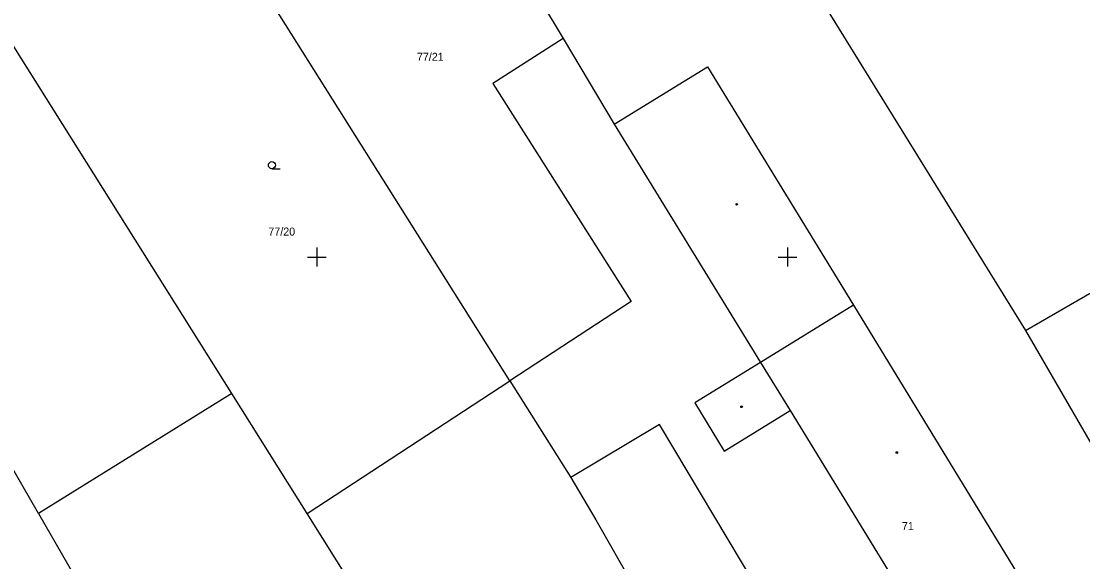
# Model space of a CAD drawing. Extents: x -703403 to -701924, y -1022520 to -1021856.
# Drawn here: x -703265.7 to -703209.3, y -1022116.2 to -1022087.5 of the extents above; entities that cross this region are included whole.
import ezdxf

# ---------------------------------------------------------------- set-up
doc = ezdxf.new("R2010")
doc.units = 0
for name, color, linetype in [('Z_hektometricka_sit', 7, 'Continuous'), ('Z_katastr_cisla_pozemkova', 7, 'Continuous'), ('Z_katastr_cisla_stavebni', 7, 'Continuous'), ('Z_katastr_hranice', 7, 'Continuous'), ('Z_katastr_vnitrni_kresba', 7, 'Continuous'), ('Z_katastr_znacky_budov', 7, 'Continuous'), ('Z_katastr_znacky_kultur', 7, 'Continuous')]:
    doc.layers.add(name, color=color, linetype=linetype)

msp = doc.modelspace()

# ---------------------------------------------------------------- linework, layer by layer
at = {"layer": 'Z_hektometricka_sit'}
for p, q in [((-703250, -1022099.5), (-703250, -1022100.5)), ((-703225, -1022099.5), (-703225, -1022100.5)), ((-703250.5, -1022100), (-703249.5, -1022100)), ((-703225.5, -1022100), (-703224.5, -1022100))]:
    msp.add_line(p, q, dxfattribs=at)
at = {"layer": 'Z_katastr_hranice'}
for p, q in [((-703239.74, -1022106.58), (-703257.17, -1022078.89)), ((-703241, -1022081.57), (-703236.91, -1022088.4)), ((-703254.52, -1022107.24), (-703270.24, -1022082.23)), ((-703223.09, -1022086.56), (-703212.35, -1022103.9)), ((-703236.91, -1022088.4), (-703240.66, -1022090.79)), ((-703236.91, -1022088.4), (-703234.2, -1022092.94)), ((-703240.66, -1022090.79), (-703233.3, -1022102.36)), ((-703234.2, -1022092.94), (-703226.43, -1022105.6)), ((-703264.78, -1022113.62), (-703274.77, -1022096.33)), ((-703233.3, -1022102.36), (-703239.74, -1022106.58)), ((-703212.35, -1022103.9), (-703205.53, -1022115.72)), ((-703226.43, -1022105.6), (-703224.86, -1022108.15)), ((-703250.51, -1022113.62), (-703239.74, -1022106.58)), ((-703239.74, -1022106.58), (-703236.51, -1022111.71)), ((-703254.52, -1022107.24), (-703264.78, -1022113.62)), ((-703250.51, -1022113.62), (-703254.52, -1022107.24)), ((-703224.86, -1022108.15), (-703216.18, -1022122.3)), ((-703236.51, -1022111.71), (-703235.18, -1022113.95)), ((-703264.78, -1022113.62), (-703258.11, -1022125.18)), ((-703247.48, -1022118.45), (-703250.51, -1022113.62)), ((-703235.18, -1022113.95), (-703226.74, -1022128.73))]:
    msp.add_line(p, q, dxfattribs=at)
at = {"layer": 'Z_katastr_vnitrni_kresba'}
for p, q in [((-703234.2, -1022092.94), (-703229.25, -1022089.9)), ((-703229.25, -1022089.9), (-703221.49, -1022102.56)), ((-703212.35, -1022103.9), (-703207.38, -1022101.01)), ((-703221.49, -1022102.56), (-703226.43, -1022105.6)), ((-703221.49, -1022102.56), (-703211.28, -1022119.27)), ((-703226.43, -1022105.6), (-703229.93, -1022107.74)), ((-703229.93, -1022107.74), (-703228.36, -1022110.3)), ((-703228.36, -1022110.3), (-703224.86, -1022108.15)), ((-703231.79, -1022108.89), (-703236.51, -1022111.71)), ((-703221.73, -1022125.72), (-703231.79, -1022108.89))]:
    msp.add_line(p, q, dxfattribs=at)
at = {"layer": 'Z_katastr_znacky_budov'}
for centre in [(-703227.702, -1022097.2), (-703227.442, -1022107.95), (-703219.192, -1022110.38)]:
    msp.add_circle(centre, 0.0437, dxfattribs=at)
at = {"layer": 'Z_katastr_znacky_kultur'}
msp.add_line((-703252.388, -1022095.31), (-703251.951, -1022095.31), dxfattribs=at)
msp.add_circle((-703252.388, -1022095.122), 0.187, dxfattribs=at)

# ---------------------------------------------------------------- texts
at = {"layer": 'Z_katastr_cisla_pozemkova'}
for s, p in [('77/21', (-703244.684, -1022089.58)), ('77/20', (-703252.573, -1022098.86))]:
    msp.add_text(s, height=0.425, dxfattribs=at).set_placement(p)
at = {"layer": 'Z_katastr_cisla_stavebni'}
msp.add_text('71', height=0.425, dxfattribs=at).set_placement((-703218.925, -1022114.5))

doc.saveas('drawing.dxf')
